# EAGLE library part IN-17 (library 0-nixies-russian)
IN-17: tiny numeric topview nixie tube
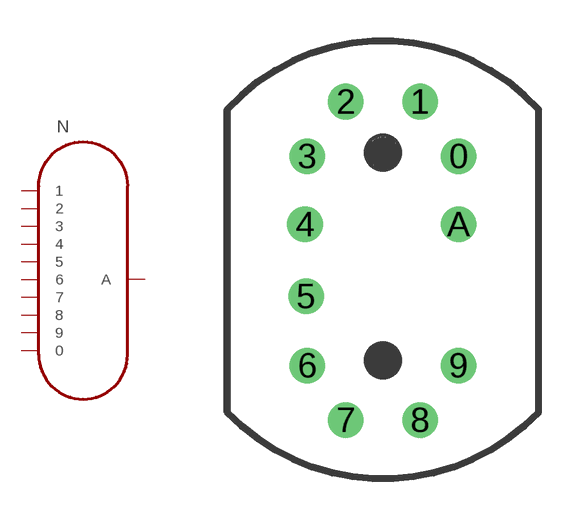
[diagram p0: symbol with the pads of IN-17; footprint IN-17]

Designator prefix N

## IN-17  [IN-17]
0  0
1  1
2  2
3  3
4  4
5  5
6  6
7  7
8  8
9  9
A  A

## Footprint IN-17 (pad centres in mm)
drill 0.8 round: 0 2.777,4; 1 1.365,6; 2 -1.365,6; 3 -2.778,4; 4 -2.858,1.5; 5 -2.818,-1.143; 6 -2.778,-3.683; 7 -1.365,-5.683; 8 1.365,-5.683; 9 2.777,-3.683; A 2.777,1.5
